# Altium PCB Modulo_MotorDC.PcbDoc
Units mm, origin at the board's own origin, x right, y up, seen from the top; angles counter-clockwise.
Board outline 127 x 101.6 mm, 2 copper layers (Top Layer, Bottom Layer); 45 components, 44 nets, 174 pads, 5 vias.
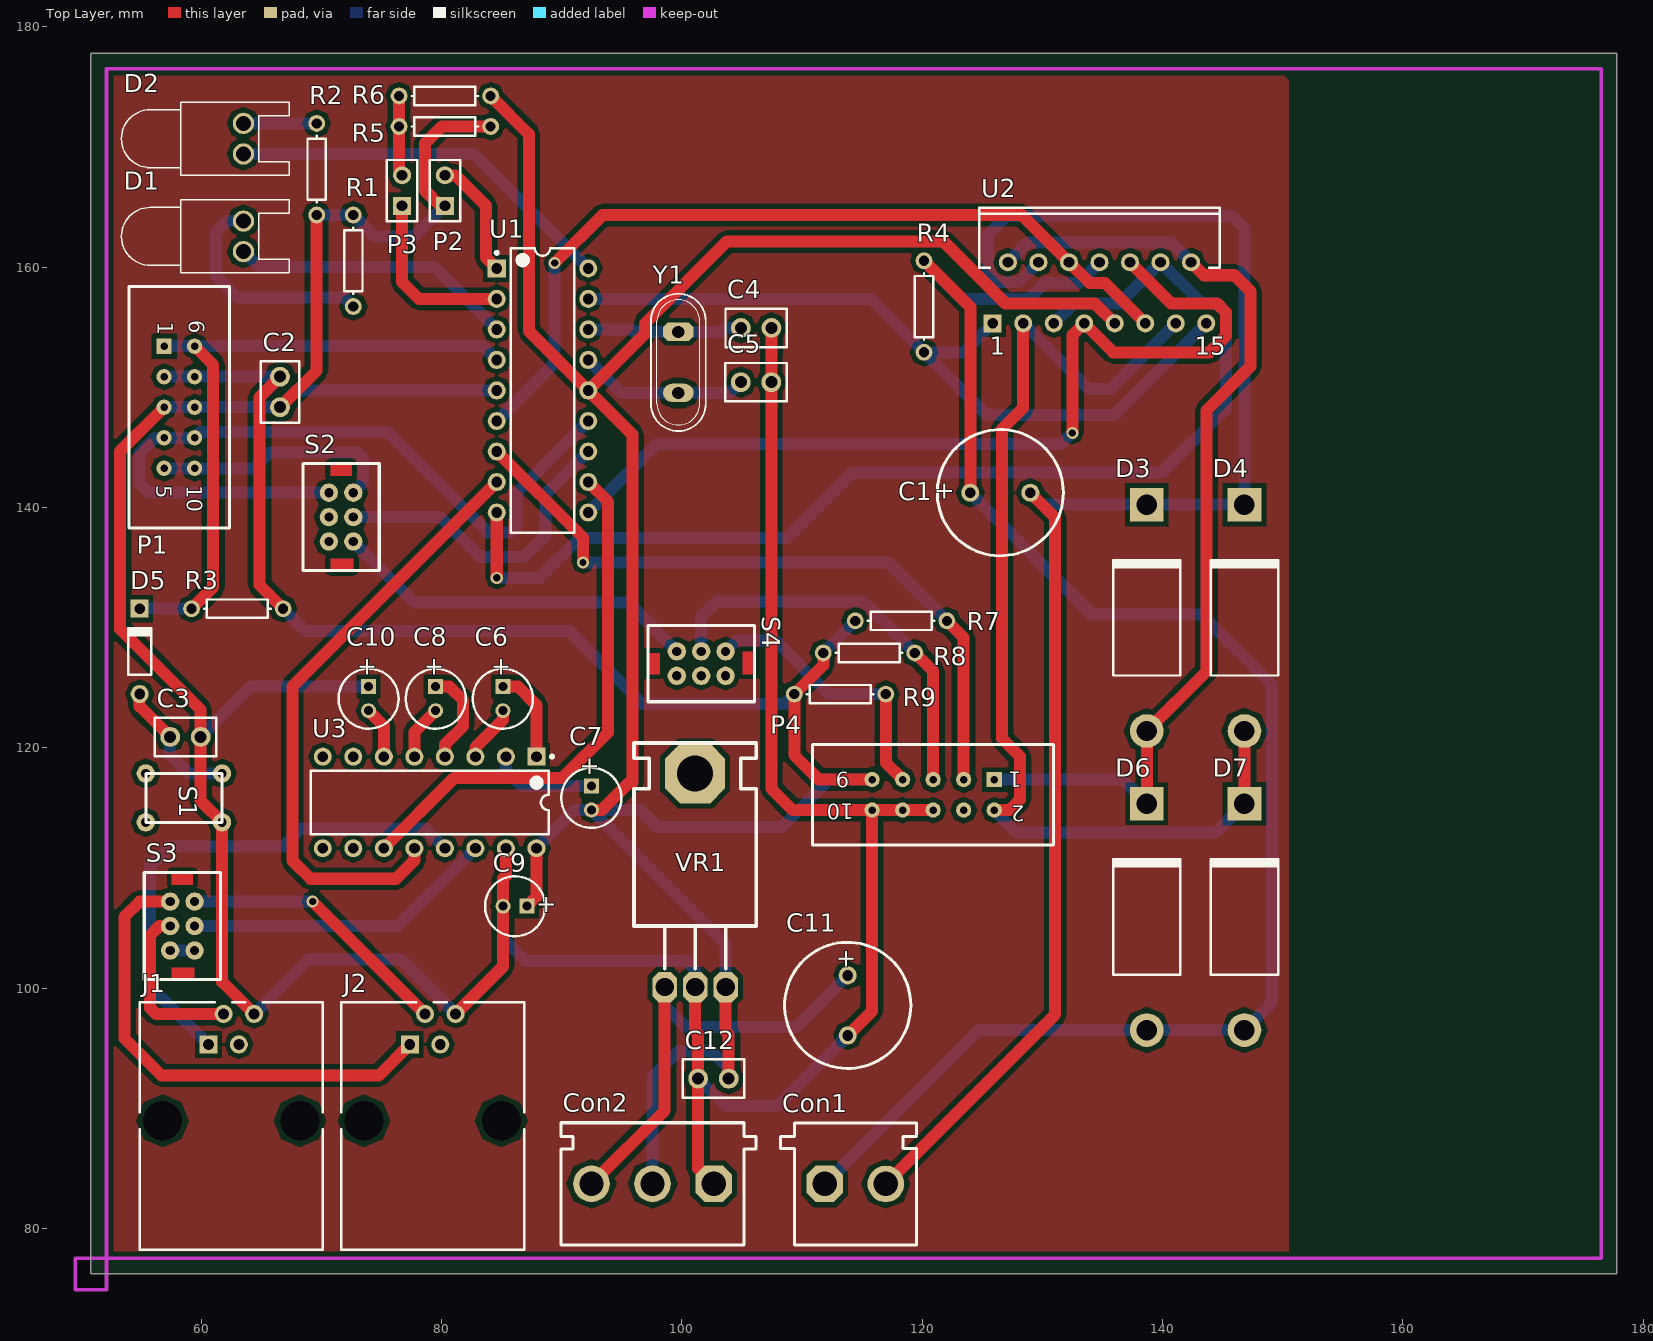
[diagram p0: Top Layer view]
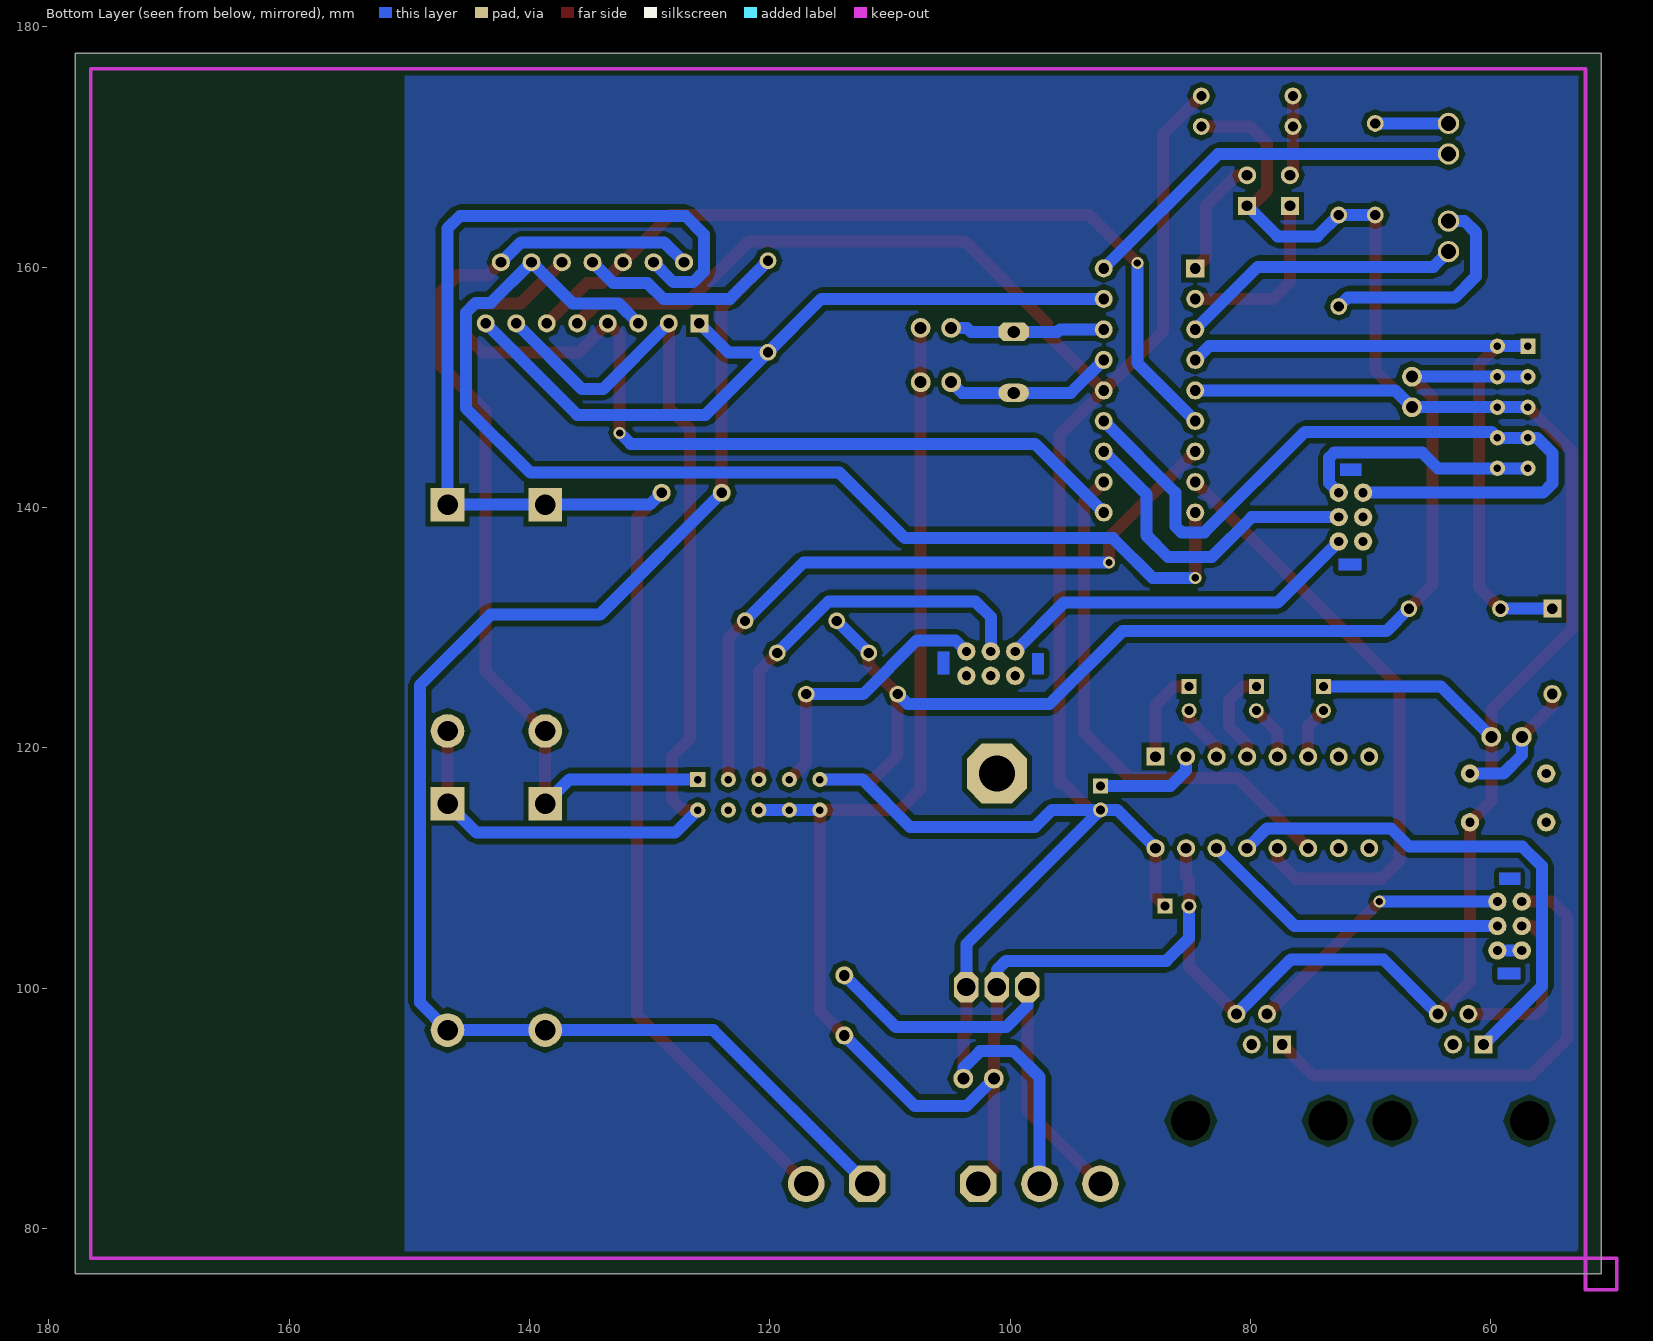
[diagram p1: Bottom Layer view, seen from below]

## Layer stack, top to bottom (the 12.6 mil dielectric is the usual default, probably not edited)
Top Layer: signal copper 0.0356
Dielectric: dielectric 0.32, FR-4, Dk 4.8
Bottom Layer: signal copper 0.0356

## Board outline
50.8,76.2 177.8,76.2 177.8,177.8 50.8,177.8

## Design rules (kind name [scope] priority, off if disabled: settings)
Clearance Clearance_1 [All] p1: gap=0.4
Clearance [All] p2: gap=0.3
PolygonConnect [All] p1: connectstyle=Relief reliefconductorwidth=0.254 reliefentries=4 polygonreliefangle="90 Angle"
RoutingVias [All] p1: holewidth=0.6 width=1 viastyle="Through Hole" minholewidth=0.711 minwidth=1.27 maxholewidth=0.711 maxwidth=1.27
SilkscreenOverComponentPads [All] p1: minsilkscreentomaskgap=0.254
SolderMaskExpansion [All] p1: expansion=0.102
Width [All] p1: maxlimit=1 minlimit=0.2 preferedwidth=1 minimp=50.000000 maximp=50.000000 favimp=50.000000
27 further rules are at their usual default settings.

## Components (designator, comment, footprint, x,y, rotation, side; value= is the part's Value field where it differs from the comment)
C1 "Cap Pol1" RB5-10.5 126.492,141.224 r180 top
C2 "Cap" CAPR2.54-5.1x3.2 66.548,149.606 r90 top
C3 "Cap" CAPR2.54-5.1x3.2 58.674,120.904 r180 top
C4 "Cap" CAPR2.54-5.1x3.2 106.172,154.94 r180 top
C5 "Cap" CAPR2.54-5.1x3.2 106.162,150.419 r180 top
C6 "Cap Pol1" CAPPR2-5x6.8 85.09,124.079 r270 top
C7 "Cap Pol1" CAPPR2-5x6.8 92.456,115.824 r270 top
C8 "Cap Pol1" CAPPR2-5x6.8 79.502,124.079 r270 top
C9 "Cap Pol1" CAPPR2-5x6.8 86.106,106.807 r180 top
C10 "Cap Pol1" CAPPR2-5x6.8 73.914,124.079 r270 top
C11 "Cap Pol1" RB5-10.5 113.792,98.552 r270 top
C12 "Cap" CAPR2.54-5.1x3.2 102.616,92.456 r0 top
Con1 "POWER_B" My_CN2 109.36,88.786 r0 top
Con2 "POWER_A" My_CN3 105.156,78.613 r180 top
D1 "LED0" LED-0 63.5,162.56 r270 top
D2 "LED0" LED-0 63.5,170.688 r270 top
D3 "Diode FR304" DIO18.84-9.6x5.6 138.684,130.81 r90 top
D4 "Diode FR304" DIO18.84-9.6x5.6 146.812,130.81 r90 top
D5 "Diode 1N4148" DIO7.1-3.9x1.9 54.864,128.016 r90 top
D6 "Diode FR304" DIO18.84-9.6x5.6 138.684,105.918 r90 top
D7 "Diode FR304" DIO18.84-9.6x5.6 146.812,105.918 r90 top
J1 "SERIAL A" 15-43-6245 62.484,78.232 r0 top
J2 "SERIAL B" 15-43-6245 79.248,78.232 r0 top
P1 "ICD2" HEADER10_5x2_B 58.166,148.336 r270 top
P2 "JUMPER VREF-" HDR1X2 80.264,165.1 r90 top
P3 "JUMPER VREF+" HDR1X2 76.708,165.1 r90 top
P4 "MOTOR DC" HEADER10_5x2_A 120.904,116.078 r180 top
R1 "Res1" AXIAL-0.3 72.644,160.528 r90 top
R2 "Res1" AXIAL-0.3 69.596,168.148 r270 top
R3 "Res1" AXIAL-0.3 62.992,131.572 r0 top
R4 "Res1" AXIAL-0.3 120.142,156.718 r90 top
R5 "Res1" AXIAL-0.3 80.264,171.704 r180 top
R6 "Res1" AXIAL-0.3 80.264,174.244 r0 top
R7 "Res1" AXIAL-0.3 118.237,130.556 r0 top
R8 "Res1" AXIAL-0.3 115.57,127.889 r0 top
R9 "Res1" AXIAL-0.3 113.157,124.46 r0 top
S1 "SW-PB" TS-063 58.547,115.824 r270 top
S2 "PROGRAM SELECTION" LD-202mini 71.628,139.192 r270 top
S3 "SERIAL CHAIN" LD-202mini 58.42,105.156 r270 top
S4 "ENCODER SELECTION" LD-202mini 101.6,127 r0 top
U1 "PIC16F88" PDIP300-P18 88.392,149.733 r0 top
U2 "L298N" Multiwatt15V 134.747,157.861 r0 top
U3 "MAX232" PE16A 78.994,115.443 r270 top
VR1 "7805" My_TO-220 98.565,100.089 r0 top
Y1 "20MHz" My_Crystal 99.695,152.07 r270 top

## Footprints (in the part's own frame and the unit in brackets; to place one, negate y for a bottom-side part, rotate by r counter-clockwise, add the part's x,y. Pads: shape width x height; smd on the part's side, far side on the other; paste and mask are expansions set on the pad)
15-43-6245 [mm] "Connector; PCB Jack, Thru-Hole; 1-Port; Unshielded without Lightpipes; Right Angle"
  rect 1.5x1.5 hole 0.9: 1(-1.905,17.07)
  round 1.5 hole 0.9: 2(-0.635,19.61) 3(0.635,17.07) 4(1.905,19.61)
  round 2.95 hole 3.25 unplated: MH1(-5.715,10.72) MH2(5.715,10.72)
  silkscreen extent -7.62,0 7.62,20.57
AXIAL-0.3 [mm] "Axial Device, Thru-Hole; 2 Leads; 0.3 in Pin Spacing"
  round 1.4 hole 0.85: 1(-3.81,0) 2(3.81,0)
  silkscreen extent -2.77,-0.76 2.77,0.76
CAPPR2-5x6.8 [mm] "Capacitor, Electrolytic, Radial; Body 5 x 6.8 mm (Dia.xH typ); Pin Spacing 2 mm (typ)"
  rect 1.25x1.25 hole 0.75: 1(-1,0)
  round 1.25 hole 0.75: 2(1,0)
  silkscreen extent -2.5,-2.5 2.5,2.5
CAPR2.54-5.1x3.2 [mm] "Capacitor, Ceramic, Thru-Hole, Dipped Radial; Body 5.1 x 3.2 mm (WxT) Pin Spacing 2.54 mm (typ)"
  round 1.65 hole 1: 1(-1.27,0) 2(1.27,0)
  silkscreen extent -2.55,-1.6 2.55,1.6
DIO7.1-3.9x1.9 [mm] "Diode, Axial; Body 3.8 x 1.9 mm (LxDia. max), Lead Dia. 0.53 mm (max)"
  round 1.5 hole 0.9: 1(-3.55,0)
  rect 1.5x1.5 hole 0.9: 2(3.55,0)
  silkscreen extent -1.95,-0.95 2.05,0.95
DIO18.84-9.6x5.6 [mm] "Diode, Axial; Body 9.5 x 5.6 mm (LxDia. max), Lead Dia. 1.32 mm (max)"
  round 2.8 hole 1.7: 1(-9.42,0)
  rect 2.8x2.8 hole 1.7: 2(9.42,0)
  silkscreen extent -4.8,-2.8 4.9,2.8
HDR1X2 [mm] "Connector; Header; 2 Position"
  rect 1.5x1.5 hole 0.9: 1(0,0)
  round 1.5 hole 0.9: 2(2.54,0)
  silkscreen extent -1.27,-1.27 3.81,1.27
HEADER10_5x2_A [mm] "Header con polaridad para 10 pines (5x2)"
  rect 1.27x1.27 hole 0.635: 1(-5.08,-1.27)
  round 1.27 hole 0.635: 2(-5.08,1.27) 3(-2.54,-1.27) 4(-2.54,1.27) 5(0,-1.27) 6(0,1.27) 7(2.54,-1.27) 8(2.54,1.27) 9(5.08,-1.27) 10(5.08,1.27)
  silkscreen extent -10.03,-4.19 10.03,4.19
HEADER10_5x2_B [mm] "Header con polaridad para 10 pines (5x2)"
  rect 1.27x1.27 hole 0.635: 1(-5.08,-1.27)
  round 1.27 hole 0.635: 2(-2.54,-1.27) 3(0,-1.27) 4(2.54,-1.27) 5(5.08,-1.27) 6(-5.08,1.27) 7(-2.54,1.27) 8(0,1.27) 9(2.54,1.27) 10(5.08,1.27)
  silkscreen extent -10.03,-4.19 10.03,4.19
LD-202mini [mil] "Doble inversor mini 90 grados"
  round 60 hole 30: 1(0,40) 2(-80,40) 3(80,40) 4(0,-40) 5(-80,-40) 6(80,-40)
  Multi-Layer region: -175,-35 -135,-35 -135,35 -175,35
  Multi-Layer region: 135,-35 175,-35 175,40 135,40
  silkscreen extent -175,-125 175,125
LED-0 [mil] "Typical INFRARED GaAs LED; 2 Leads"
  round 70 hole 50: 1(50,0) 2(-50,0)
  silkscreen extent -120,-400 120,150
Multiwatt15V [mm] "TO, Thru-Hole, Vertical, Heatsink Mounted; 15 Bent Staggered Leads; Pitch 1.27 mm"
  rect 1.5x1.5 hole 0.9: 1(-8.89,-2.54)
  round 1.5 hole 0.9: 2(-7.62,2.54) 3(-6.35,-2.54) 4(-5.08,2.54) 5(-3.81,-2.54) 6(-2.54,2.54) 7(-1.27,-2.54) 8(0,2.54) 9(1.27,-2.54) 10(2.54,2.54) 11(3.81,-2.54) 12(5.08,2.54) 13(6.35,-2.54) 14(7.62,2.54) 15(8.89,-2.54)
  silkscreen extent -10,2.09 10,7.09
My_CN2 [mil]
  oct 120x120 hole 80: 1(99.5,-200.5)
  round 120 hole 80: 2(299.5,-200.5)
  silkscreen extent -45,-400 400,0
My_CN3 [mil]
  oct 120x120 hole 80: 1(99.5,-200.5)
  round 120 hole 80: 2(299.5,-200.5) 3(499.5,-200.5)
  silkscreen extent -40,-400 600,0
My_Crystal [mil]
  oct 60x100 hole 40: 1(-100,0)
  oval 60x100 hole 40: 2(100,0)
  silkscreen extent -225,-90 225,90
My_TO-220 [mil]
  oct 196.85x196.85 hole 118.11: 0(99.49,699.49)
  oct 80x100 hole 60: 1(-0.5,-0.5) 2(99.5,-0.5) 3(199.5,-0.5)
  silkscreen extent -100,60 299,799
PDIP300-P18 [mm] "DIP, 18-Leads, Row Spacing 7.62mm, Pitch 2.54mm, Body 22.9x6.6mm"
  rect 1.5x1.5 hole 0.9: 1(-3.81,10.16)
  round 1.5 hole 0.9: 2(-3.81,7.62) 3(-3.81,5.08) 4(-3.81,2.54) 5(-3.81,0) 6(-3.81,-2.54) 7(-3.81,-5.08) 8(-3.81,-7.62) 9(-3.81,-10.16) 10(3.81,-10.16) 11(3.81,-7.62) 12(3.81,-5.08) 13(3.81,-2.54) 14(3.81,0) 15(3.81,2.54) 16(3.81,5.08) 17(3.81,7.62) 18(3.81,10.16)
  silkscreen extent -3.93,-11.85 2.65,11.85, body extent -3.6,-11.8 3.6,11.8, height 5.34
PE16A [mm] "DIP, 16-Leads, Row Spacing 7.62mm, Pitch 2.54mm, Body 19.18x6.99mm"
  rect 1.5x1.5 hole 0.9: 1(-3.81,8.89)
  round 1.5 hole 0.9: 2(-3.81,6.35) 3(-3.81,3.81) 4(-3.81,1.27) 5(-3.81,-1.27) 6(-3.81,-3.81) 7(-3.81,-6.35) 8(-3.81,-8.89) 9(3.81,-8.89) 10(3.81,-6.35) 11(3.81,-3.81) 12(3.81,-1.27) 13(3.81,1.27) 14(3.81,3.81) 15(3.81,6.35) 16(3.81,8.89)
  silkscreen extent -3.93,-9.9 2.65,10.32, body extent -3.3,-9.9 3.3,9.9, height 5.08
RB5-10.5 [mm] "Motor, General Kind; 2 Leads"
  round 1.5 hole 0.9: 1(-2.5,0) 2(2.5,0)
  silkscreen extent -5.25,-5.25 5.25,5.25
TS-063 [mil] "Boton normal abierto"
  round 60 hole 30: 1(80,125) 1(80,-125) 2(-80,125) 2(-80,-125)
  silkscreen extent -80,-125 80,125

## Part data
C1 C6 C7 C8 C9 C10 C11: "Polarized Capacitor (Radial)"
C2 C3 C4 C5 C12: "Capacitor"
Con1: library part "CON2 pin blue", "Connector blue screw"
Con2: library part "CON3 pin Green", "Connector green screw"
D1 D2: "Typical INFRARED GaAs LED"
D3 D4 D6 D7: library part "Diode 1N5404", "3 Amp General Purpose Rectifier"
D5: "High Conductance Fast Diode"
J1 J2: library part 15-43-6245, "Right Angle, Standard Profile, RJ45-Keyed, Flange Mount PCB Jack"
P1: library part "Header 5X2A", "Header, 5-Pin, Dual row"
P2 P3: library part "Header 2", "Header, 2-Pin"
P4: library part "Header 5X2", "Header, 5-Pin, Dual row"
R1 R2 R3 R4 R5 R6 R7 R8 R9: "Resistor"
S1: "Switch"
S2 S3: library part SW-DPDT, "Double-Pole, Double-Throw Switch"
S4: library part SW-SPDT, "SPDT Subminiature Toggle Switch, Right Angle Mounting, Vertical Actuation"
U1: library part PIC16F88-E/P, "Enhanced FLASH Microcontroller with nanoWatt Technology, 10-Bit A/D, 4K (x14-Bit words) FLASH, 368 Bytes RAM, 18-Pin PDIP, Standard VDD Range, Extended Temperature"
U2: "Dual Full Bridge Driver"
U3: library part MAX232ACPE, "+5V Powered, Multi-Channel RS-232 Driver/Receiver"
VR1: library part "Volt Reg", "Voltage Regulator"
Y1: library part XTAL, "Crystal Oscillator"

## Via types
v1: diameter 1, hole 0.6, Top Layer to Bottom Layer, 5 vias

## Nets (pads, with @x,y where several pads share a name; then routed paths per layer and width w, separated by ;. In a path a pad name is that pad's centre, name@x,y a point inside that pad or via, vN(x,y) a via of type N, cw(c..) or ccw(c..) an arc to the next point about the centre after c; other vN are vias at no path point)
"+5V VCC": C2.2 C7.2 C9.1 C12.2 Con2.2 P1.2 P1.7 P4.9 R3.2 R6.2 R7.1 R8.1 R9.1 U1.14 U2.9 U3.16 VR1.3 | length 297
  Top Layer w1: C2.2 64.821,149.149 64.821,133.553 R3.2 ; R6.2 87.249,171.069 87.249,154.686 U1.14 ; C9.1 87.884,107.585 U3.16 ; C7.2 93.345,114.824 95.631,117.11 ; 95.885,117.094 95.885,146.05 U1.14 ; VR1.3 103.632,96.393 103.886,96.139 C12.2 ; R8.1 111.76,126.873 R9.1 109.347,119.38 111.379,117.348 P4.9 ; U2.9 134.366,156.972 126.924,156.972 121.768,162.128 103.733,162.128 96.901,155.296 96.901,154.432 U1.14
  Bottom Layer w1: P1.2 P1.7 C2.2 ; R3.2 68.656,129.718 90.627,129.718 96.698,123.647 108.534,123.647 R9.1 ; U3.16 91.075,114.824 C7.2 ; Con2.2 97.549,92.596 99.695,94.742 102.489,94.742 103.886,93.345 C12.2 ; VR1.3 103.632,103.648 C7.2 ; R8.1 R7.1 ; P4.9 112.268,117.348 108.331,113.411 97.917,113.411 96.504,114.824 C7.2
"+12V MOTOR": C1.1 Con1.2 D3.2 D4.2 U2.4 | length 136.2
  Top Layer w1: Con1.2 131.064,97.79 131.064,139.152 C1.1
  Bottom Layer w1: C1.1 129.986,140.23 D3.2 D4.2 146.812,163.22 145.796,164.236 127,164.236 125.477,162.713 125.477,159.639 126.365,158.751 128.017,158.751 U2.4
"+V LOGIC": C11.1 Con2.3 VR1.1 | length 38.2
  Top Layer w1: Con2.3 98.552,89.789 VR1.1
  Bottom Layer w1: VR1.1 98.552,98.526 100.33,96.749 109.489,96.749 C11.1
ENCODER: S2.3 S4.2 | length 30.7
  Bottom Layer w1: S2.3 77.724,132.08 95.504,132.08 S4.2
ENCODER_A: P4.7 R9.2 S4.3 | length 23.3
  Top Layer w1: R9.2 116.967,118.745 P4.7
  Bottom Layer w1: S4.3 104.546,128.93 107.747,128.93 112.217,124.46 R9.2
ENCODER_B: P4.5 R8.2 S4.1 | length 34.1
  Top Layer w1: R8.2 120.904,126.365 P4.5
  Bottom Layer w1: S4.1 101.6,130.886 102.87,132.156 115.113,132.156 R8.2
GND: C2.1 C3.1 C4.1 C5.1 C9.2 C10.1 C11.2 C12.1 Con2.1 J1.4 J2.4 P1.3 P1.8 P2.1 P4.6 P4.8 P4.10 R1.2 R2.2 R5.1 S1.1@61.722,113.792 U1.5 U3.15 VR1.2 | length 309.8
  Top Layer w1: P1.3 53.213,144.653 53.213,129.896 59.944,123.165 C3.1 59.944,115.57 61.722,113.792 61.722,100.509 J1.4 ; C2.1 69.596,151.384 R2.2 ; P2.1 79.883,165.1 78.613,166.37 78.613,170.307 80.01,171.704 R5.1 ; J2.4 85.106,101.795 C9.2 85.106,109.093 85.344,109.331 U3.15 ; VR1.2 101.092,96.393 101.346,96.139 C12.1 101.346,84.988 Con2.1 ; C4.1 107.442,152.664 107.432,152.654 C5.1 107.432,116.596 109.22,114.808 P4.10 ; C11.2 115.824,98.084 P4.10 ; P4.6 P4.8 P4.10
  Bottom Layer w1: P1.3 P1.8 C2.1 67.945,149.733 U1.5 ; C3.1 64.119,125.079 C10.1 ; J1.4 68.934,102.387 76.608,102.387 J2.4 ; R2.2 R1.2 74.422,162.56 77.724,162.56 P2.1 ; C9.2 85.106,104.14 86.986,102.26 100.33,102.26 101.092,101.498 VR1.2 ; C12.1 103.632,90.17 107.91,90.17 C11.2 ; P4.10 P4.8 P4.6
ICD2_CLK: P1.5 P1.10 S2.2 | length 20.5
  Bottom Layer w1: P1.5 64.389,143.256 65.684,144.551 73.025,144.551 73.431,144.145 73.431,142.011 S2.2
ICD2_CLK/ENCODER: S2.1 U1.12 | length 26.6
  Bottom Layer w1: S2.1 79.883,139.192 83.185,135.89 86.868,135.89 88.64,137.662 88.64,141.091 U1.12
ICD2_DATA: P1.4 P1.9 S2.5 U1.13 | length 65.6
  Bottom Layer w1: S2.5 55.626,141.224 54.864,141.986 54.864,144.526 56.134,145.796 P1.9 59.931,146.291 75.452,146.291 83.82,137.923 85.726,137.923 86.233,138.43 86.233,141.224 U1.13
ICD2_DATA/ENCODER: S2.4
INPUT_A: U1.10 U2.7 U2.10 | length 77.6
  Top Layer w1: v1(132.486,146.202) 132.486,154.33 U2.7 135.89,152.908 143.89,152.908 145.287,154.305 145.287,156.21 144.525,156.972 140.716,156.972 U2.10
  Bottom Layer w1: U1.10 97.917,145.288 131.572,145.288 v1(132.486,146.202)
INPUT_B: U1.9 U2.5 U2.12 | length 98.1
  Top Layer w1: v1(84.582,134.137) U1.9
  Bottom Layer w1: v1(84.582,134.137) 88.135,134.137 91.44,137.442 108.74,137.442 114.198,142.9 139.929,142.9 145.288,148.26 145.288,156.21 144.475,157.023 143.205,157.023 U2.12 136.398,156.972 132.588,156.972 U2.5
LED1: D1.1 U1.3 | length 23.8
  Bottom Layer w1: D1.1 64.77,160.02 79.375,160.02 U1.3
LED2: D2.1 U1.18 | length 32.6
  Bottom Layer w1: D2.1 82.677,169.418 U1.18
MAX_TX: S3.1 U3.14 | length 26.1
  Bottom Layer w1: S3.1 76.327,105.156 U3.14
MCLR: D5.2 P1.1 P1.6 R3.1 U1.4 | length 55.7
  Top Layer w1: R3.1 60.985,133.375 60.985,151.867 P1.6
  Bottom Layer w1: D5.2 55.982,131.566 55.988,131.572 R3.1 ; P1.1 P1.6 83.439,153.416 U1.4
"MOTOR GND": C1.2 Con1.1 D6.1 D7.1 R4.2 U2.8 | length 139.7
  Top Layer w1: R4.2 123.992,156.678 C1.2
  Bottom Layer w1: Con1.1 124.692,96.498 D6.1 D7.1 149.123,98.809 149.123,125.197 143.231,131.089 134.127,131.089 C1.2 ; R4.2 123.319,157.351 128.853,157.351 130.177,158.675 133.021,158.675 U2.8
MOTOR_A: D4.1 D7.2 P4.2 U2.3 U2.13 | length 89.4
  Top Layer w1: P4.2 127.254,114.808 128.143,115.697 128.143,119.253 126.619,120.777 126.619,146.507 128.397,148.285 U2.3 ; D7.2 D4.1
  Bottom Layer w1: P4.2 127.864,112.928 144.402,112.928 D7.2 ; U2.3 133.858,149.86 135.636,149.86 U2.13
MOTOR_B: D3.1 D6.2 P4.1 U2.2 U2.14 | length 82.3
  Top Layer w1: D6.2 D3.1 143.662,126.368 143.662,148.082 147.32,151.74 147.32,157.988 145.987,159.321 143.447,159.321 U2.14
  Bottom Layer w1: P4.1 136.674,117.348 D6.2 ; U2.2 128.778,162.052 140.716,162.052 U2.14
MOTOR_IDX: P4.3 R7.2 U1.7 | length 58.3
  Top Layer w1: U1.7 91.77,137.465 v1(91.77,135.407) ; R7.2 123.444,129.159 P4.3
  Bottom Layer w1: v1(91.77,135.407) 117.196,135.407 R7.2
NetC3_2: C3.2 D5.1 S1.2@61.722,117.856 | length 11.1
  Top Layer w1: D5.1 54.864,123.444 C3.2
  Bottom Layer w1: C3.2 57.404,119.38 58.928,117.856 S1.2@61.722,117.856
NetC4_2: C4.2 U1.16 Y1.1 | length 12.9
  Bottom Layer w1: U1.16 95.834,154.813 96.037,154.61 Y1.1 103.265,154.61 103.595,154.94 C4.2
NetC5_2: C5.2 U1.15 Y1.2 | length 14.2
  Bottom Layer w1: U1.15 94.945,149.53 Y1.2 104.003,149.53 C5.2
NetC6_1: C6.1 U3.1 | length 7.7
  Top Layer w1: C6.1 86.36,125.079 87.884,123.555 U3.1
NetC6_2: C6.2 U3.3 | length 4.8
  Top Layer w1: U3.3 82.804,120.015 85.09,122.301 C6.2
NetC7_1: C7.1 U3.2 | length 8.8
  Bottom Layer w1: U3.2 85.344,118.11 86.63,116.824 C7.1
NetC8_1: C8.1 U3.4 | length 8.1
  Top Layer w1: C8.1 80.645,125.079 81.788,123.936 81.788,121.793 80.264,120.269 U3.4
NetC8_2: C8.2 U3.5 | length 4.6
  Top Layer w1: U3.5 77.724,121.301 C8.2
NetC10_2: C10.2 U3.6 | length 4.4
  Top Layer w1: C10.2 75.184,121.809 U3.6
NetD1_2: D1.2 R1.1 | length 18.8
  Bottom Layer w1: D1.2 62.16,163.83 61.214,162.884 61.214,159.233 62.992,157.455 71.907,157.455 R1.1
NetD2_2: D2.2 R2.1 | length 6.1
  Bottom Layer w1: D2.2 R2.1
NetP3_2: P3.2 R5.2 R6.1 | length 6.7
  Top Layer w1: R6.1 R5.2 76.454,167.894 P3.2
NetS3_3: S3.3 S3.6 | length 2
  Bottom Layer w1: S3.6 S3.3
PIC_RX: U1.8 U3.12 | length 51
  Top Layer w1: U3.12 77.724,110.617 76.2,109.093 69.088,109.093 67.564,110.617 67.564,125.095 U1.8
PIC_TX: U1.11 U3.11 | length 44.2
  Top Layer w1: U3.11 81.026,117.475 90.043,117.475 93.852,121.284 93.852,140.463 U1.11
PWM_ENABLE: U1.6 U2.6 U2.11 | length 69.7
  Top Layer w1: v1(89.408,160.35) 93.396,164.338 128.27,164.338 U2.6 133.922,158.686 135.192,158.686 U2.11
  Bottom Layer w1: U1.6 89.408,152.019 v1(89.408,160.35)
SENSE: R4.1 U1.17 U2.1 U2.15 | length 65.3
  Bottom Layer w1: U1.17 115.697,157.353 R4.1 ; U2.1 123.444,152.908 R4.1 ; U2.15 136.017,147.701 125.349,147.701 R4.1
SERIAL_A_RX: J1.2 S3.4 | length 14.3
  Top Layer w1: S3.4 56.515,105.156 55.742,104.383 55.742,98.335 56.235,97.842 J1.2
SERIAL_A_TX: J1.1 U3.13 | length 43.4
  Bottom Layer w1: J1.1 55.728,100.153 55.728,110.134 57.353,111.76 66.777,111.76 68.301,113.284 78.613,113.284 U3.13
SERIAL_B_RX: J2.2 S3.2 | length 23
  Top Layer w1: v1(69.267,107.188) J2.2
  Bottom Layer w1: S3.2 v1(69.267,107.188)
SERIAL_B_TX: J2.1 S3.5 | length 40.6
  Top Layer w1: S3.5 54.864,107.188 53.594,105.918 53.594,95.809 56.693,92.71 74.751,92.71 J2.1
VREF+: P3.1 U1.2 | length 14.8
  Top Layer w1: P3.1 76.708,158.75 78.105,157.353 U1.2
VREF-: P2.2 U1.1 | length 10.1
  Top Layer w1: P2.2 81.153,167.64 83.685,165.108 83.685,160.79 U1.1
pads on no net: J1.3 J1.MH1 J1.MH2 J2.3 J2.MH1 J2.MH2 P4.4 S1.1@55.372,113.792 S1.2@55.372,117.856 S2.6 S4.4 S4.5 S4.6 U3.7 U3.8 U3.9 U3.10 VR1.0

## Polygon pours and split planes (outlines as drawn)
no net on Top Layer "Top Layer-No Net" (solid, pour order 1000): 52.451,78.105 52.451,176.149 149.86,176.149 150.241,175.768 150.495,175.514 150.495,77.978
no net on Bottom Layer "Top Layer-No Net" (solid, pour order 1001): 52.695,78.105 52.695,175.905 150.358,175.905 150.358,78.115 150.368,78.105

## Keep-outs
Keep-Out Layer:
  lines w0.3: 52.1,77.5 49.5,77.5 49.5,74.9 52.1,74.9 52.1,77.5 ; 52.1,77.5 52.1,176.5 176.5,176.5 176.5,77.5 52.1,77.5

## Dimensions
50.8,76.2 to 52.1,77.5 on Mechanical 1
50.8,76.2 to 52.1,77.5 on Mechanical 1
